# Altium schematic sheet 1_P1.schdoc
size 307 x 218 mm; Symbol: Drawing-Symbol_A4; Device: Drawing-Symbol_A4; Company: 嘉立创EDA; Version: V1.0; Page Size: A4; @Project Name: IP6829Test; @Page Count: 1; @Update Date: 2025-07-18; @Create Date: 2025-07-17; @Schematic Name: Schematic3; @Page No: 1; @Page Name: P1; @Create Time: 16:47:51; @Update Time: 00:47:51; Width: 1170; Height: 825; Region Start: 1; X Region Count: 6; Y Region Count: 4; Blade Width: 10; Title Block Position: 3; @Board Name: Board3
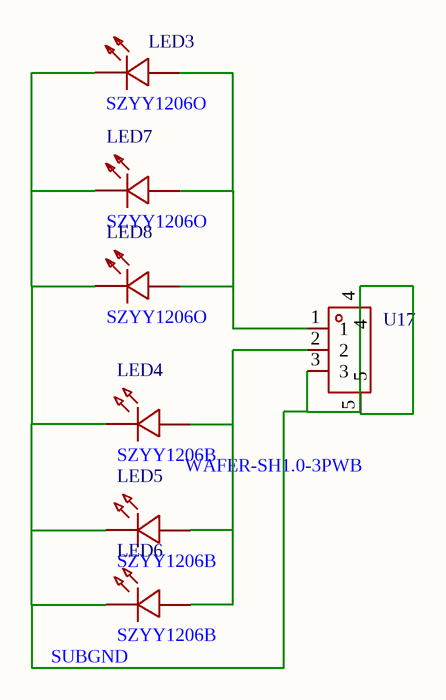
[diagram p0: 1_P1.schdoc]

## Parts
LED3  SZYY1206O  [LED1206-RD_ORANGE]
LED4  SZYY1206B  [LED1206-RD_BLUE]
LED5  SZYY1206B  [LED1206-RD_BLUE]
LED6  SZYY1206B  [LED1206-RD_BLUE]
LED7  SZYY1206O  [LED1206-RD_ORANGE]
LED8  SZYY1206O  [LED1206-RD_ORANGE]
U17  WAFER-SH1.0-3PWB  [CONN-SMD_3P-P1.00_WAFER-SH1.0-3PWB]

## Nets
SUBGND: LED3.1(K) LED4.1 LED5.1 LED6.1 LED7.1(K) LED8.1(K) U17.3 U17.4 U17.5
NetLED3_2: LED3.2(A) LED7.2(A) LED8.2(A) U17.1
NetLED4_2: LED4.2 LED5.2 LED6.2 U17.2

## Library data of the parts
LED3 LED7 LED8 = SZYY1206O: Manufacturer: yongyu(永裕光电); Add into BOM: yes; Emitted Color: 橙色; Power Dissipation: 40mW; Forward Current: 10mA; Dominant Wavelength: 598nm~608nm; Peak Wavelength: 612nm; Lens Color: 无色透明透镜; Viewing Angle: 120°
LED4-LED6 = SZYY1206B: Manufacturer: yongyu(永裕光电); Add into BOM: yes; Emitted Color: 蓝色; Power Dissipation: 100mW; Forward Current: 5mA; Dominant Wavelength: 460nm~475nm; Peak Wavelength: 469nm; Lens Color: 无色透明透镜; Viewing Angle: 120°
U17 = WAFER-SH1.0-3PWB: Manufacturer: XUNPU(讯普); Add into BOM: yes; Pins Structure: 1x3P; Pitch: 1mm; Reference Series: SH; Number of PINs Per Row: 3; Current Rating: 1A; Voltage Rating: 50V; Plastic Material: LCP; Supplementary Features: 辅助焊脚; Z-Height of the Board: 3.15mm; X-Length of Bottom Edge on Board (Spacing Line): 5.35mm; Y-Width of Bottom Edge on Board: 5.05mm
